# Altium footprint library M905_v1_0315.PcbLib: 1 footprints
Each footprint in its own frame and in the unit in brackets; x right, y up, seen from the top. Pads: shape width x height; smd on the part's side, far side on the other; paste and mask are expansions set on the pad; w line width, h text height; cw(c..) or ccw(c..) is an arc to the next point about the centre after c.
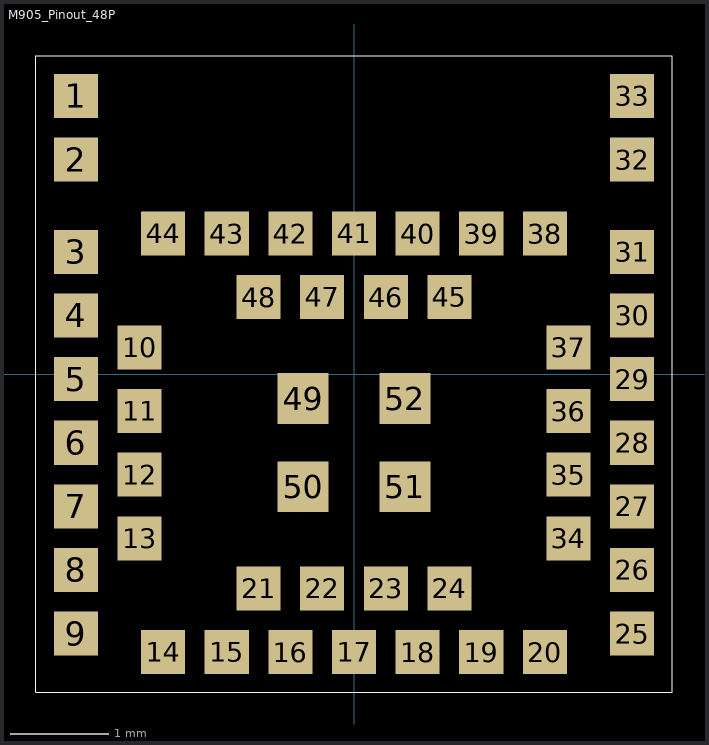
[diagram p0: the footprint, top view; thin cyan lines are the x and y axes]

## M905_Pinout_48P [mm] "M905_Pinout_48P"
pads (52):
  rect 0.45x0.45 smd mask-0.05: 1(-2.84,2.84) 2(-2.84,2.19) 3(-2.84,1.248) 4(-2.84,0.598) 5(-2.84,-0.052) 6(-2.84,-0.702) 7(-2.84,-1.352) 8(-2.84,-2.002) 9(-2.84,-2.652) 10(-2.19,0.272) 11(-2.19,-0.378) 12(-2.19,-1.028) 13(-2.19,-1.678) 14(-1.95,-2.84) 15(-1.3,-2.84) 16(-0.65,-2.84) 17(0,-2.84) 18(0.65,-2.84) 19(1.3,-2.84) 20(1.95,-2.84) 21(-0.975,-2.19) 22(-0.325,-2.19) 23(0.325,-2.19) 24(0.975,-2.19) 25(2.84,-2.652) 26(2.84,-2.002) 27(2.84,-1.352) 28(2.84,-0.702) 29(2.84,-0.052) 30(2.84,0.598) 31(2.84,1.248) 32(2.84,2.19) 33(2.84,2.84) 34(2.19,-1.678) 35(2.19,-1.028) 36(2.19,-0.378) 37(2.19,0.272) 38(1.95,1.435) 39(1.3,1.435) 40(0.65,1.435) 41(0,1.435) 42(-0.65,1.435) 43(-1.3,1.435) 44(-1.95,1.435) 45(0.975,0.785) 46(0.325,0.785) 47(-0.325,0.785) 48(-0.975,0.785)
  rect 0.52x0.52 smd mask-0.05: 49(-0.52,-0.252) 50(-0.52,-1.152) 51(0.52,-1.152) 52(0.52,-0.252)
Top Overlay:
  lines w0: -3.25,-3.25 3.25,-3.25 3.25,3.25 -3.25,3.25 -3.25,-3.25
  lines w0.01: -3.25,-3.25 -3.25,3.25 3.25,3.25 3.25,-3.25 -3.25,-3.25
